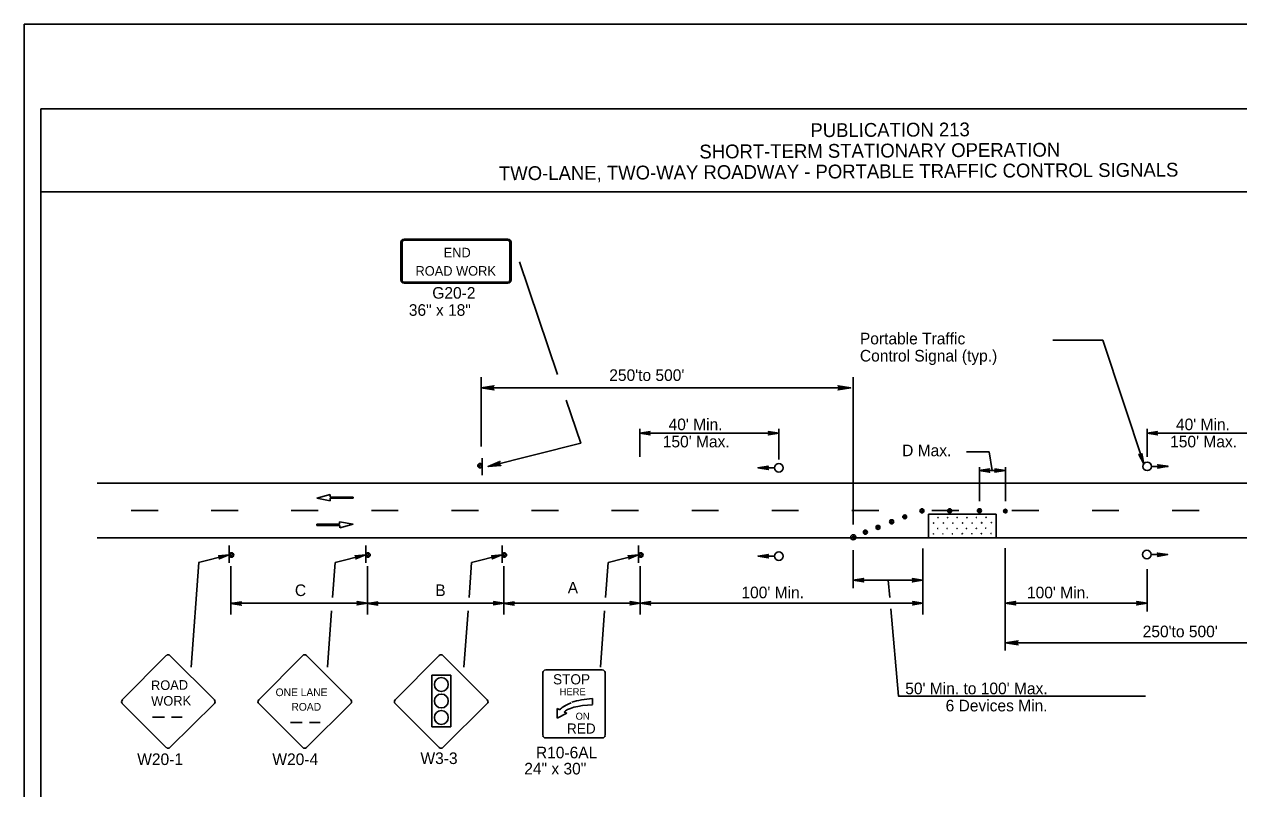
# Model space of a CAD drawing. Extents: x -14145 to -13521, y 30244 to 30661.
# Drawn here: x -13722.17 to -13700.23, y 30355.49 to 30369.31 of the extents above; entities that cross this region are included whole.
import ezdxf

# ---------------------------------------------------------------- set-up
doc = ezdxf.new("R2010")
doc.units = 0
for name, color, linetype in [('1', 7, 'Continuous'), ('10', 7, 'Continuous'), ('2', 7, 'Continuous'), ('3', 7, 'Continuous'), ('4', 7, 'Continuous'), ('61', 7, 'Continuous')]:
    doc.layers.add(name, color=color, linetype=linetype)

msp = doc.modelspace()

# ---------------------------------------------------------------- linework, layer by layer
at = {"layer": '1'}
for p, q in [((-13715.369, 30365.368), (-13715.369, 30364.68)), ((-13715.344, 30365.368), (-13715.344, 30364.68)), ((-13713.435, 30365.419), (-13715.308, 30365.419)), ((-13713.435, 30365.419), (-13715.308, 30365.419)), ((-13713.435, 30365.404), (-13715.308, 30365.404)), ((-13713.435, 30365.404), (-13715.308, 30365.404)), ((-13713.399, 30364.68), (-13713.399, 30365.368)), ((-13713.374, 30364.68), (-13713.374, 30365.368)), ((-13715.308, 30364.643), (-13713.435, 30364.643)), ((-13715.308, 30364.628), (-13713.435, 30364.628)), ((-13703.586, 30363.593), (-13702.683, 30363.593)), ((-13702.683, 30363.593), (-13701.946, 30361.362)), ((-13713.916, 30361.671), (-13713.916, 30362.928)), ((-13713.916, 30362.734), (-13707.24, 30362.734)), ((-13707.195, 30360.266), (-13707.195, 30362.928)), ((-13711.052, 30361.487), (-13711.052, 30361.996)), ((-13711.052, 30361.914), (-13708.54, 30361.914)), ((-13708.539, 30361.438), (-13708.539, 30361.994)), ((-13701.884, 30361.487), (-13701.884, 30361.996)), ((-13701.884, 30361.914), (-13699.372, 30361.914)), ((-13713.9, 30361.153), (-13713.9, 30361.465)), ((-13713.9, 30361.153), (-13713.9, 30361.465)), ((-13704.738, 30361.575), (-13705.148, 30361.575)), ((-13704.738, 30361.575), (-13704.682, 30361.237)), ((-13704.917, 30361.237), (-13704.447, 30361.237)), ((-13704.916, 30360.685), (-13704.916, 30361.3)), ((-13704.446, 30360.685), (-13704.446, 30361.3)), ((-13720.855, 30361.008), (-13691.771, 30361.008)), ((-13716.649, 30360.804), (-13716.89, 30360.738)), ((-13716.649, 30360.759), (-13716.649, 30360.804)), ((-13716.233, 30360.759), (-13716.649, 30360.759)), ((-13716.233, 30360.737), (-13716.233, 30360.759)), ((-13716.89, 30360.738), (-13716.647, 30360.692)), ((-13716.647, 30360.692), (-13716.647, 30360.737)), ((-13716.647, 30360.737), (-13716.233, 30360.737)), ((-13719.757, 30360.516), (-13720.243, 30360.516)), ((-13718.31, 30360.516), (-13718.796, 30360.516)), ((-13716.863, 30360.516), (-13717.349, 30360.516)), ((-13716.233, 30360.268), (-13716.476, 30360.314)), ((-13716.476, 30360.314), (-13716.476, 30360.269)), ((-13715.416, 30360.516), (-13715.902, 30360.516)), ((-13713.969, 30360.516), (-13714.455, 30360.516)), ((-13712.522, 30360.516), (-13713.008, 30360.516)), ((-13711.075, 30360.516), (-13711.561, 30360.516)), ((-13709.628, 30360.516), (-13710.114, 30360.516)), ((-13708.181, 30360.516), (-13708.667, 30360.516)), ((-13706.734, 30360.516), (-13707.22, 30360.516)), ((-13704.609, 30360.45), (-13705.833, 30360.45)), ((-13705.833, 30360.024), (-13705.833, 30360.45)), ((-13705.287, 30360.516), (-13705.773, 30360.516)), ((-13704.609, 30360.024), (-13704.609, 30360.45)), ((-13703.84, 30360.516), (-13704.326, 30360.516)), ((-13702.393, 30360.516), (-13702.879, 30360.516)), ((-13700.946, 30360.516), (-13701.432, 30360.516)), ((-13716.476, 30360.269), (-13716.89, 30360.269)), ((-13716.89, 30360.269), (-13716.89, 30360.247)), ((-13716.89, 30360.247), (-13716.474, 30360.247)), ((-13716.474, 30360.201), (-13716.233, 30360.268)), ((-13716.474, 30360.247), (-13716.474, 30360.201)), ((-13720.855, 30360.024), (-13691.771, 30360.024)), ((-13718.47, 30359.885), (-13718.47, 30359.573)), ((-13716.004, 30359.885), (-13716.004, 30359.573)), ((-13716.004, 30359.885), (-13716.004, 30359.573)), ((-13713.538, 30359.885), (-13713.538, 30359.573)), ((-13713.538, 30359.885), (-13713.538, 30359.573)), ((-13711.072, 30359.885), (-13711.072, 30359.573)), ((-13711.072, 30359.885), (-13711.072, 30359.573)), ((-13719.023, 30359.578), (-13718.476, 30359.718)), ((-13716.557, 30359.578), (-13716.01, 30359.718)), ((-13714.091, 30359.578), (-13713.544, 30359.718)), ((-13711.625, 30359.578), (-13711.078, 30359.718)), ((-13707.195, 30359.115), (-13707.195, 30359.798)), ((-13705.934, 30358.636), (-13705.934, 30359.83)), ((-13704.447, 30357.986), (-13704.447, 30359.836)), ((-13719.161, 30357.686), (-13719.022, 30359.577)), ((-13718.44, 30358.636), (-13718.44, 30359.51)), ((-13716.603, 30358.943), (-13716.556, 30359.577)), ((-13715.974, 30358.636), (-13715.974, 30359.51)), ((-13714.137, 30358.943), (-13714.09, 30359.577)), ((-13713.508, 30358.636), (-13713.508, 30359.51)), ((-13711.671, 30358.943), (-13711.624, 30359.577)), ((-13711.042, 30358.636), (-13711.042, 30359.51)), ((-13701.886, 30358.69), (-13701.886, 30359.455)), ((-13707.195, 30359.256), (-13705.94, 30359.256)), ((-13715.974, 30358.84), (-13718.44, 30358.84)), ((-13713.508, 30358.84), (-13715.974, 30358.84)), ((-13711.042, 30358.84), (-13713.508, 30358.84)), ((-13711.042, 30358.84), (-13705.934, 30358.84)), ((-13704.447, 30358.84), (-13701.886, 30358.84)), ((-13716.695, 30357.686), (-13716.621, 30358.701)), ((-13714.229, 30357.686), (-13714.155, 30358.701)), ((-13711.763, 30357.686), (-13711.689, 30358.701)), ((-13704.447, 30358.125), (-13697.869, 30358.125)), ((-13719.608, 30357.897), (-13720.403, 30357.094)), ((-13718.739, 30357.094), (-13719.542, 30357.897)), ((-13717.142, 30357.897), (-13717.937, 30357.094)), ((-13716.273, 30357.094), (-13717.076, 30357.897)), ((-13714.676, 30357.897), (-13715.471, 30357.094)), ((-13713.807, 30357.094), (-13714.61, 30357.897)), ((-13714.81, 30356.604), (-13714.81, 30357.542)), ((-13714.81, 30357.542), (-13714.468, 30357.542)), ((-13714.468, 30357.542), (-13714.468, 30356.604)), ((-13712.805, 30356.452), (-13712.805, 30357.588)), ((-13712.75, 30357.635), (-13711.732, 30357.635)), ((-13711.678, 30357.588), (-13711.678, 30356.452)), ((-13720.403, 30357.028), (-13719.608, 30356.233)), ((-13719.542, 30356.233), (-13718.739, 30357.028)), ((-13717.937, 30357.028), (-13717.142, 30356.233)), ((-13717.076, 30356.233), (-13716.273, 30357.028)), ((-13715.471, 30357.028), (-13714.676, 30356.233)), ((-13714.61, 30356.233), (-13713.807, 30357.028)), ((-13711.907, 30357.007), (-13711.909, 30357.118)), ((-13712.542, 30356.935), (-13712.542, 30356.764)), ((-13712.497, 30356.913), (-13712.542, 30356.935)), ((-13712.542, 30356.764), (-13712.371, 30356.85)), ((-13712.371, 30356.85), (-13712.418, 30356.873)), ((-13719.854, 30356.78), (-13719.643, 30356.78)), ((-13719.511, 30356.78), (-13719.318, 30356.78)), ((-13717.365, 30356.686), (-13717.154, 30356.686)), ((-13717.022, 30356.686), (-13716.828, 30356.686)), ((-13714.468, 30356.604), (-13714.81, 30356.604)), ((-13711.732, 30356.405), (-13712.75, 30356.405))]:
    msp.add_line(p, q, dxfattribs=at)
for points in [[(-13710.878, 30361.89), (-13710.884, 30361.902), (-13711.052, 30361.914), (-13710.878, 30361.89), (-13710.866, 30361.884), (-13711.052, 30361.914), (-13710.884, 30361.92), (-13710.878, 30361.932), (-13711.052, 30361.914), (-13710.866, 30361.944), (-13710.878, 30361.932)], [(-13708.72, 30361.938), (-13708.714, 30361.926), (-13708.54, 30361.914), (-13708.72, 30361.938), (-13708.726, 30361.944), (-13708.54, 30361.914), (-13708.714, 30361.908), (-13708.72, 30361.896), (-13708.54, 30361.914), (-13708.726, 30361.884), (-13708.72, 30361.896)], [(-13701.71, 30361.89), (-13701.716, 30361.902), (-13701.884, 30361.914), (-13701.71, 30361.89), (-13701.698, 30361.884), (-13701.884, 30361.914), (-13701.716, 30361.92), (-13701.71, 30361.932), (-13701.884, 30361.914), (-13701.698, 30361.944), (-13701.71, 30361.932)], [(-13701.982, 30361.54), (-13701.993, 30361.527), (-13701.946, 30361.362), (-13701.982, 30361.54), (-13701.977, 30361.547), (-13701.946, 30361.362), (-13702.011, 30361.52), (-13702.024, 30361.526), (-13701.946, 30361.362), (-13702.036, 30361.53), (-13702.024, 30361.526)], [(-13708.736, 30361.268), (-13708.748, 30361.28), (-13708.916, 30361.289), (-13708.736, 30361.268), (-13708.731, 30361.256), (-13708.916, 30361.289), (-13708.748, 30361.298), (-13708.742, 30361.31), (-13708.916, 30361.289), (-13708.729, 30361.316), (-13708.742, 30361.31)], [(-13704.743, 30361.213), (-13704.749, 30361.225), (-13704.917, 30361.237), (-13704.743, 30361.213), (-13704.731, 30361.207), (-13704.917, 30361.237), (-13704.749, 30361.243), (-13704.743, 30361.255), (-13704.917, 30361.237), (-13704.731, 30361.267), (-13704.743, 30361.255)], [(-13704.627, 30361.261), (-13704.621, 30361.249), (-13704.447, 30361.237), (-13704.627, 30361.261), (-13704.633, 30361.267), (-13704.447, 30361.237), (-13704.621, 30361.231), (-13704.627, 30361.219), (-13704.447, 30361.237), (-13704.633, 30361.207), (-13704.627, 30361.219)], [(-13701.686, 30361.295), (-13701.674, 30361.307), (-13701.506, 30361.316), (-13701.686, 30361.295), (-13701.691, 30361.283), (-13701.506, 30361.316), (-13701.674, 30361.325), (-13701.68, 30361.337), (-13701.506, 30361.316), (-13701.693, 30361.343), (-13701.68, 30361.337)], [(-13718.656, 30359.694), (-13718.644, 30359.682), (-13718.476, 30359.718), (-13718.656, 30359.694), (-13718.662, 30359.7), (-13718.476, 30359.718), (-13718.638, 30359.664), (-13718.644, 30359.652), (-13718.476, 30359.718), (-13718.65, 30359.64), (-13718.644, 30359.652)], [(-13716.19, 30359.694), (-13716.178, 30359.682), (-13716.01, 30359.718), (-13716.19, 30359.694), (-13716.196, 30359.7), (-13716.01, 30359.718), (-13716.172, 30359.664), (-13716.178, 30359.652), (-13716.01, 30359.718), (-13716.184, 30359.64), (-13716.178, 30359.652)], [(-13713.724, 30359.694), (-13713.712, 30359.682), (-13713.544, 30359.718), (-13713.724, 30359.694), (-13713.73, 30359.7), (-13713.544, 30359.718), (-13713.706, 30359.664), (-13713.712, 30359.652), (-13713.544, 30359.718), (-13713.718, 30359.64), (-13713.712, 30359.652)], [(-13711.258, 30359.694), (-13711.246, 30359.682), (-13711.078, 30359.718), (-13711.258, 30359.694), (-13711.264, 30359.7), (-13711.078, 30359.718), (-13711.24, 30359.664), (-13711.246, 30359.652), (-13711.078, 30359.718), (-13711.252, 30359.64), (-13711.246, 30359.652)], [(-13708.735, 30359.672), (-13708.747, 30359.684), (-13708.915, 30359.693), (-13708.735, 30359.672), (-13708.73, 30359.66), (-13708.915, 30359.693), (-13708.747, 30359.702), (-13708.741, 30359.714), (-13708.915, 30359.693), (-13708.728, 30359.72), (-13708.741, 30359.714)], [(-13701.691, 30359.7), (-13701.679, 30359.712), (-13701.511, 30359.721), (-13701.691, 30359.7), (-13701.696, 30359.688), (-13701.511, 30359.721), (-13701.679, 30359.73), (-13701.685, 30359.742), (-13701.511, 30359.721), (-13701.698, 30359.748), (-13701.685, 30359.742)], [(-13707.015, 30359.238), (-13707.027, 30359.25), (-13707.195, 30359.256), (-13707.015, 30359.238), (-13707.009, 30359.226), (-13707.195, 30359.256), (-13707.027, 30359.268), (-13707.021, 30359.28), (-13707.195, 30359.256), (-13707.009, 30359.286), (-13707.021, 30359.28)], [(-13706.535, 30358.942), (-13706.563, 30359.255)], [(-13706.12, 30359.28), (-13706.108, 30359.262), (-13705.94, 30359.256), (-13706.12, 30359.28), (-13706.126, 30359.286), (-13705.94, 30359.256), (-13706.108, 30359.25), (-13706.114, 30359.232), (-13705.94, 30359.256), (-13706.126, 30359.226), (-13706.114, 30359.232)], [(-13718.26, 30358.81), (-13718.266, 30358.822), (-13718.44, 30358.834), (-13718.26, 30358.81), (-13718.254, 30358.804), (-13718.44, 30358.834), (-13718.266, 30358.84), (-13718.26, 30358.852), (-13718.44, 30358.834), (-13718.254, 30358.864), (-13718.26, 30358.852)], [(-13716.154, 30358.864), (-13716.148, 30358.846), (-13715.974, 30358.84), (-13716.154, 30358.864), (-13716.16, 30358.87), (-13715.974, 30358.84), (-13716.148, 30358.834), (-13716.154, 30358.816), (-13715.974, 30358.84), (-13716.16, 30358.81), (-13716.154, 30358.816)], [(-13715.794, 30358.81), (-13715.8, 30358.822), (-13715.974, 30358.834), (-13715.794, 30358.81), (-13715.788, 30358.804), (-13715.974, 30358.834), (-13715.8, 30358.84), (-13715.794, 30358.852), (-13715.974, 30358.834), (-13715.788, 30358.864), (-13715.794, 30358.852)], [(-13713.688, 30358.864), (-13713.682, 30358.846), (-13713.508, 30358.84), (-13713.688, 30358.864), (-13713.694, 30358.87), (-13713.508, 30358.84), (-13713.682, 30358.834), (-13713.688, 30358.816), (-13713.508, 30358.84), (-13713.694, 30358.81), (-13713.688, 30358.816)], [(-13713.328, 30358.81), (-13713.334, 30358.822), (-13713.508, 30358.834), (-13713.328, 30358.81), (-13713.322, 30358.804), (-13713.508, 30358.834), (-13713.334, 30358.84), (-13713.328, 30358.852), (-13713.508, 30358.834), (-13713.322, 30358.864), (-13713.328, 30358.852)], [(-13711.222, 30358.864), (-13711.216, 30358.846), (-13711.042, 30358.84), (-13711.222, 30358.864), (-13711.228, 30358.87), (-13711.042, 30358.84), (-13711.216, 30358.834), (-13711.222, 30358.816), (-13711.042, 30358.84), (-13711.228, 30358.81), (-13711.222, 30358.816)], [(-13710.868, 30358.816), (-13710.874, 30358.828), (-13711.042, 30358.84), (-13710.868, 30358.816), (-13710.856, 30358.81), (-13711.042, 30358.84), (-13710.874, 30358.846), (-13710.868, 30358.858), (-13711.042, 30358.84), (-13710.856, 30358.87), (-13710.868, 30358.858)], [(-13706.114, 30358.864), (-13706.102, 30358.846), (-13705.934, 30358.84), (-13706.114, 30358.864), (-13706.12, 30358.87), (-13705.934, 30358.84), (-13706.102, 30358.834), (-13706.108, 30358.816), (-13705.934, 30358.84), (-13706.12, 30358.81), (-13706.108, 30358.816)], [(-13704.267, 30358.822), (-13704.279, 30358.834), (-13704.447, 30358.84), (-13704.267, 30358.822), (-13704.261, 30358.81), (-13704.447, 30358.84), (-13704.279, 30358.852), (-13704.273, 30358.864), (-13704.447, 30358.84), (-13704.261, 30358.87), (-13704.273, 30358.864)], [(-13702.066, 30358.864), (-13702.054, 30358.846), (-13701.886, 30358.84), (-13702.066, 30358.864), (-13702.072, 30358.87), (-13701.886, 30358.84), (-13702.054, 30358.834), (-13702.06, 30358.816), (-13701.886, 30358.84), (-13702.072, 30358.81), (-13702.06, 30358.816)], [(-13701.912, 30357.159), (-13706.376, 30357.159), (-13706.517, 30358.736)]]:
    msp.add_lwpolyline(points, dxfattribs=at)
for centre, radius in [((-13713.94, 30361.327), 0.0408), ((-13705.954, 30360.511), 0.037), ((-13705.954, 30360.511), 0.037), ((-13705.454, 30360.511), 0.037), ((-13704.914, 30360.513), 0.0353), ((-13704.446, 30360.505), 0.0331), ((-13706.501, 30360.312), 0.038), ((-13706.503, 30360.308), 0.0155), ((-13706.264, 30360.402), 0.0346), ((-13706.263, 30360.398), 0.0101), ((-13705.956, 30360.509), 0.0172), ((-13705.956, 30360.509), 0.0172), ((-13705.662, 30360.387), 0.00272), ((-13705.489, 30360.388), 0.00272), ((-13705.456, 30360.509), 0.0172), ((-13705.315, 30360.389), 0.00272), ((-13705.14, 30360.388), 0.00272), ((-13704.969, 30360.39), 0.00272), ((-13704.911, 30360.514), 0.014), ((-13704.794, 30360.393), 0.00272), ((-13704.447, 30360.506), 0.012), ((-13706.975, 30360.124), 0.037), ((-13706.974, 30360.122), 0.0194), ((-13706.747, 30360.211), 0.036), ((-13706.75, 30360.217), 0.0161), ((-13705.747, 30360.094), 0.00272), ((-13705.742, 30360.289), 0.00272), ((-13705.667, 30360.191), 0.00272), ((-13705.572, 30360.095), 0.00272), ((-13705.567, 30360.291), 0.00272), ((-13705.496, 30360.191), 0.00272), ((-13705.399, 30360.095), 0.00272), ((-13705.395, 30360.289), 0.00272), ((-13705.319, 30360.192), 0.00272), ((-13705.225, 30360.096), 0.00272), ((-13705.219, 30360.291), 0.00272), ((-13705.146, 30360.192), 0.00272), ((-13705.051, 30360.097), 0.00272), ((-13705.046, 30360.29), 0.00272), ((-13704.97, 30360.193), 0.00272), ((-13704.879, 30360.1), 0.00272), ((-13704.878, 30360.097), 0.00272), ((-13704.874, 30360.295), 0.00272), ((-13704.872, 30360.292), 0.00272), ((-13704.799, 30360.197), 0.00272), ((-13704.704, 30360.101), 0.00272), ((-13704.699, 30360.297), 0.00272), ((-13707.194, 30360.033), 0.0455), ((-13707.193, 30360.032), 0.0167), ((-13718.43, 30359.711), 0.0408), ((-13715.964, 30359.711), 0.0408), ((-13713.498, 30359.711), 0.0408), ((-13711.032, 30359.711), 0.0408), ((-13714.638, 30357.37), 0.126), ((-13714.638, 30357.073), 0.126), ((-13714.638, 30356.775), 0.126)]:
    msp.add_circle(centre, radius, dxfattribs=at)
for centre, radius, start, end in [((-13713.935, 30361.319), 0.0214, 9.521, 4.2501), ((-13718.435, 30359.719), 0.0214, 189.521, 184.2501), ((-13715.969, 30359.719), 0.0214, 189.521, 184.2501), ((-13713.503, 30359.719), 0.0214, 189.521, 184.2501), ((-13711.037, 30359.719), 0.0214, 189.521, 184.2501), ((-13719.574, 30357.862), 0.0465, 45, 135), ((-13717.109, 30357.862), 0.0465, 45, 135), ((-13714.643, 30357.862), 0.0465, 45, 135), ((-13720.369, 30357.059), 0.0465, 135, 225), ((-13718.771, 30357.059), 0.0465, 315, 45), ((-13717.904, 30357.06), 0.0465, 135, 225), ((-13716.306, 30357.059), 0.0465, 315, 45), ((-13715.438, 30357.06), 0.0465, 135, 225), ((-13713.84, 30357.059), 0.0465, 315, 45), ((-13719.574, 30356.264), 0.0465, 225, 315), ((-13717.109, 30356.264), 0.0465, 225, 315), ((-13714.643, 30356.264), 0.0465, 225, 315)]:
    msp.add_arc(centre, radius, start, end, dxfattribs=at)
for centre, major_axis, ratio, start_param, end_param in [((-13715.31, 30365.367), (0.0609, 0), 0.839899, 1.570796, 3.141593), ((-13715.31, 30365.367), (0, -0.0365), 0.999938, 3.141593, 4.712389), ((-13713.438, 30365.367), (-0.0609, 0), 0.839899, 3.141593, 4.712389), ((-13713.438, 30365.367), (0, 0.0365), 0.999938, 4.712389, 6.283185), ((-13715.31, 30364.679), (0.0609, 0), 0.839899, 3.141593, 4.712389), ((-13715.31, 30364.679), (0, -0.0365), 0.999938, 4.712389, 6.283185), ((-13713.438, 30364.679), (0, 0.0365), 0.999938, 3.141593, 4.712389), ((-13713.438, 30364.679), (-0.0609, 0), 0.839899, 1.570796, 3.141593), ((-13712.75, 30357.587), (-0.0541, 0), 0.866667, 4.712389, 6.283185), ((-13711.731, 30357.587), (-0.0541, 0), 0.866667, 3.141593, 4.712389), ((-13711.873, 30357.106), (0.632, 0.211), 0.13767, 2.24751, 2.61166), ((-13711.865, 30356.895), (0.626, 0.024), 0.356316, 1.625555, 2.277861), ((-13711.898, 30356.868), (0.626, 0.024), 0.356316, 2.688881, 2.833949), ((-13712.256, 30356.77), (-0.29, 0), 0.866667, 5.239865, 5.534055), ((-13711.898, 30356.868), (0.526, 0.021), 0.259792, 1.574563, 2.966983), ((-13712.75, 30356.451), (0.0541, 0), 0.866667, 3.141593, 4.712389), ((-13711.731, 30356.451), (0.0541, 0), 0.866667, 4.712389, 6.283185)]:
    msp.add_ellipse(centre, major_axis=major_axis, ratio=ratio, start_param=start_param, end_param=end_param, dxfattribs=at)
at = {"layer": '10'}
for p, q in [((-13721.874, 30367.777), (-13690.422, 30367.777)), ((-13721.874, 30345.207), (-13721.874, 30367.777)), ((-13721.874, 30366.277), (-13690.422, 30366.277))]:
    msp.add_line(p, q, dxfattribs=at)
at = {"layer": '2'}
for p, q in [((-13708.915, 30361.288), (-13708.615, 30361.288)), ((-13701.506, 30361.315), (-13701.806, 30361.315)), ((-13708.915, 30359.692), (-13708.615, 30359.692)), ((-13701.511, 30359.72), (-13701.811, 30359.72))]:
    msp.add_line(p, q, dxfattribs=at)
for centre in [(-13708.538, 30361.288), (-13701.883, 30361.315), (-13708.537, 30359.692), (-13701.888, 30359.72)]:
    msp.add_circle(centre, 0.0775, dxfattribs=at)
at = {"layer": '3'}
for points in [[(-13713.226, 30365.011), (-13712.536, 30362.973)], [(-13713.698, 30362.707), (-13713.706, 30362.723), (-13713.916, 30362.734), (-13713.698, 30362.707), (-13713.687, 30362.698), (-13713.916, 30362.734), (-13713.706, 30362.745), (-13713.699, 30362.76), (-13713.916, 30362.734), (-13713.687, 30362.771), (-13713.699, 30362.76)], [(-13707.458, 30362.762), (-13707.45, 30362.746), (-13707.24, 30362.734), (-13707.458, 30362.762), (-13707.469, 30362.771), (-13707.24, 30362.734), (-13707.45, 30362.724), (-13707.457, 30362.708), (-13707.24, 30362.734), (-13707.469, 30362.698), (-13707.457, 30362.708)], [(-13712.379, 30362.509), (-13712.117, 30361.733), (-13713.793, 30361.314)], [(-13713.575, 30361.34), (-13713.586, 30361.353), (-13713.793, 30361.314), (-13713.575, 30361.34), (-13713.562, 30361.333), (-13713.793, 30361.314), (-13713.592, 30361.375), (-13713.588, 30361.392), (-13713.793, 30361.314), (-13713.579, 30361.405), (-13713.588, 30361.392)], [(-13704.229, 30358.098), (-13704.237, 30358.113), (-13704.447, 30358.125), (-13704.229, 30358.098), (-13704.217, 30358.088), (-13704.447, 30358.125), (-13704.237, 30358.135), (-13704.229, 30358.151), (-13704.447, 30358.125), (-13704.217, 30358.161), (-13704.229, 30358.151)]]:
    msp.add_lwpolyline(points, dxfattribs=at)
at = {"layer": '61'}
msp.add_lwpolyline([(-13722.174, 30369.307), (-13689.174, 30369.307), (-13689.174, 30343.807), (-13722.174, 30343.807)], close=True, dxfattribs=at)

# ---------------------------------------------------------------- texts
at = {"layer": '1'}
for s, height, p in [('END', 0.173, (-13714.595, 30365.093)), ('ROAD WORK', 0.173, (-13715.104, 30364.762)), ('STOP', 0.1838, (-13712.619, 30357.373)), ('ONE LANE', 0.1386, (-13717.632, 30357.161)), ('HERE', 0.1268, (-13712.5, 30357.177)), ('ROAD', 0.1389, (-13717.347, 30356.898)), ('ON', 0.1268, (-13712.211, 30356.734)), ('RED', 0.1838, (-13712.368, 30356.483))]:
    msp.add_text(s, height=height, dxfattribs=at).set_placement(p)
for s, height, rotation, p in [('ROAD', 0.1735, 0.7566, (-13719.883, 30357.269)), ('WORK', 0.1733, 0.7588, (-13719.879, 30356.984))]:
    msp.add_text(s, height=height, rotation=rotation, dxfattribs=at).set_placement(p)
at = {"layer": '2'}
for s, p in [('G20-2', (-13714.801, 30364.346)), ('36" x 18"', (-13715.225, 30364.036)), ('Portable Traffic', (-13707.074, 30363.52)), ('Control Signal (typ.)', (-13707.074, 30363.21)), ("250'to 500'", (-13711.603, 30362.859)), ("40' Min.", (-13710.531, 30361.968)), ("40' Min.", (-13701.363, 30361.968)), ("150' Max.", (-13710.636, 30361.658)), ("150' Max.", (-13701.468, 30361.658)), ('D Max.', (-13706.311, 30361.498)), ('A', (-13712.354, 30359.017)), ('C', (-13717.284, 30358.97)), ('B', (-13714.747, 30358.97)), ("100' Min.", (-13709.215, 30358.93)), ("100' Min.", (-13704.055, 30358.929)), ("250'to 500'", (-13701.964, 30358.225)), ("50' Min. to 100' Max.", (-13706.255, 30357.195)), ('6 Devices Min.', (-13705.525, 30356.885)), ('W3-3', (-13715.015, 30355.933)), ('R10-6AL', (-13712.928, 30356.036)), ('W20-1', (-13720.133, 30355.915)), ('W20-4', (-13717.691, 30355.915)), ('24" x 30"', (-13713.139, 30355.745))]:
    msp.add_text(s, height=0.21, dxfattribs=at).set_placement(p)
at = {"layer": '4'}
for s, p in [('PUBLICATION 213', (-13707.968, 30367.266)), ('SHORT-TERM STATIONARY OPERATION', (-13709.974, 30366.88)), ('TWO-LANE, TWO-WAY ROADWAY - PORTABLE TRAFFIC CONTROL SIGNALS', (-13713.596, 30366.487))]:
    msp.add_text(s, height=0.25, rotation=0.31, dxfattribs=at).set_placement(p)

doc.saveas('drawing.dxf')
